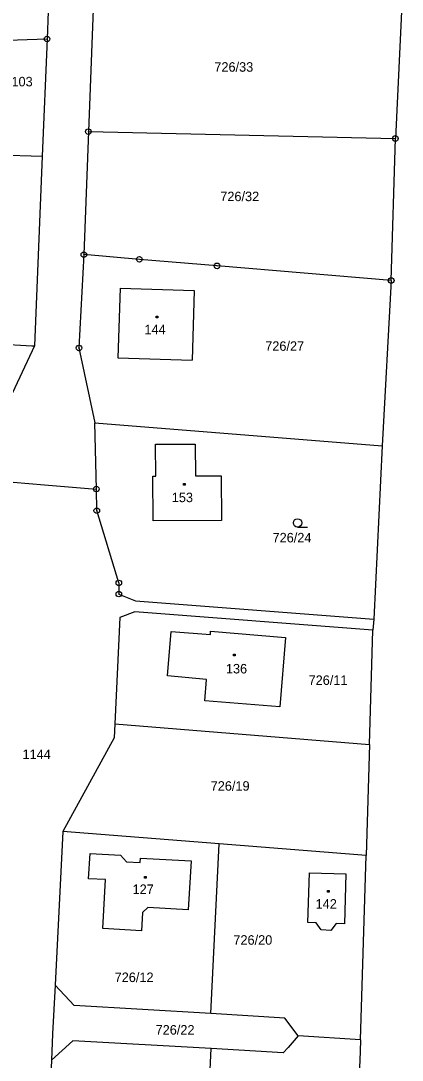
# Model space of a CAD drawing. Extents: x -794142 to -791199, y -1109267 to -1105626.
# Drawn here: x -793214.3 to -793146.2, y -1107931.8 to -1107745.8 of the extents above; entities that cross this region are included whole.
import ezdxf

# ---------------------------------------------------------------- set-up
doc = ezdxf.new("R2010")
doc.units = 0
for name, color, linetype in [('Vrstva 1', 7, 'Continuous'), ('Vrstva 14', 7, 'Continuous'), ('Vrstva 15', 7, 'Continuous'), ('Vrstva 23', 7, 'Continuous'), ('Vrstva 25', 7, 'Continuous'), ('Vrstva 28', 7, 'Continuous')]:
    doc.layers.add(name, color=color, linetype=linetype)

msp = doc.modelspace()

# ---------------------------------------------------------------- linework, layer by layer
at = {"layer": 'Vrstva 1'}
for p, q in [((-793146.16, -1107741.39), (-793147.38, -1107766.85)), ((-793209.44, -1107744.14), (-793209.64, -1107749.04)), ((-793201.42, -1107743.69), (-793202.25, -1107765.62)), ((-793221.25, -1107749.43), (-793209.64, -1107749.04)), ((-793209.64, -1107749.04), (-793210.51, -1107769.99)), ((-793202.25, -1107765.62), (-793203.07, -1107787.63)), ((-793202.25, -1107765.62), (-793147.38, -1107766.85)), ((-793148.12, -1107792.27), (-793147.38, -1107766.85)), ((-793220.37, -1107769.71), (-793210.51, -1107769.99)), ((-793210.51, -1107769.99), (-793211.88, -1107803.94)), ((-793203.07, -1107787.63), (-793203.93, -1107804.33)), ((-793193.13, -1107788.47), (-793203.07, -1107787.63)), ((-793179.26, -1107789.64), (-793193.13, -1107788.47)), ((-793148.12, -1107792.27), (-793179.26, -1107789.64)), ((-793148.12, -1107792.27), (-793149.73, -1107821.84)), ((-793196.55, -1107793.64), (-793196.97, -1107806.08)), ((-793196.55, -1107793.64), (-793183.32, -1107794.07)), ((-793183.32, -1107794.07), (-793183.72, -1107806.51)), ((-793211.88, -1107803.94), (-793223.04, -1107827.73)), ((-793222.21, -1107803.43), (-793212.38, -1107803.92)), ((-793212.38, -1107803.92), (-793211.88, -1107803.94)), ((-793203.93, -1107804.33), (-793201.08, -1107817.72)), ((-793196.97, -1107806.08), (-793183.72, -1107806.51)), ((-793201.08, -1107817.72), (-793149.73, -1107821.84)), ((-793200.83, -1107829.58), (-793201.08, -1107817.72)), ((-793190.24, -1107821.57), (-793183.16, -1107821.52)), ((-793183.16, -1107821.52), (-793183.11, -1107827.22)), ((-793190.2, -1107827.27), (-793190.24, -1107821.57)), ((-793149.73, -1107821.84), (-793151.23, -1107852.83)), ((-793223.04, -1107827.73), (-793210.07, -1107828.81)), ((-793210.07, -1107828.81), (-793200.83, -1107829.58)), ((-793190.67, -1107835.29), (-793190.73, -1107827.27)), ((-793190.73, -1107827.27), (-793190.2, -1107827.27)), ((-793183.11, -1107827.22), (-793178.5, -1107827.18)), ((-793178.5, -1107827.18), (-793178.43, -1107835.19)), ((-793200.75, -1107833.44), (-793200.83, -1107829.58)), ((-793196.81, -1107846.37), (-793200.75, -1107833.44)), ((-793178.43, -1107835.19), (-793190.67, -1107835.29)), ((-793196.81, -1107846.37), (-793196.81, -1107848.36)), ((-793196.81, -1107848.36), (-793193.82, -1107849.58)), ((-793193.82, -1107849.58), (-793151.23, -1107852.83)), ((-793196.63, -1107852.57), (-793197.54, -1107871.61)), ((-793193.97, -1107851.57), (-793196.63, -1107852.57)), ((-793151.38, -1107854.83), (-793193.97, -1107851.57)), ((-793151.23, -1107852.83), (-793151.38, -1107854.83)), ((-793152, -1107875.31), (-793151.38, -1107854.83)), ((-793188.09, -1107863.02), (-793187.43, -1107855.04)), ((-793187.43, -1107855.04), (-793180.45, -1107855.6)), ((-793180.45, -1107855.6), (-793180.4, -1107855.03)), ((-793180.4, -1107855.03), (-793166.99, -1107856.13)), ((-793166.99, -1107856.13), (-793168.04, -1107868.53)), ((-793181.12, -1107863.64), (-793188.09, -1107863.02)), ((-793181.44, -1107867.46), (-793181.12, -1107863.64)), ((-793168.04, -1107868.53), (-793181.44, -1107867.46)), ((-793197.54, -1107871.61), (-793197.66, -1107874.08)), ((-793197.54, -1107871.61), (-793152, -1107875.31)), ((-793197.66, -1107874.08), (-793206.8, -1107890.84)), ((-793152, -1107875.31), (-793152.61, -1107895.15)), ((-793206.8, -1107890.84), (-793208.2, -1107918.34)), ((-793178.86, -1107893.06), (-793206.8, -1107890.84)), ((-793180.34, -1107923.43), (-793178.86, -1107893.06)), ((-793152.61, -1107895.15), (-793178.86, -1107893.06)), ((-793202.21, -1107899.32), (-793201.93, -1107894.81)), ((-793201.93, -1107894.81), (-793196.51, -1107895.09)), ((-793196.51, -1107895.09), (-793195.46, -1107896.27)), ((-793192.97, -1107896.42), (-793192.92, -1107895.61)), ((-793192.92, -1107895.61), (-793183.9, -1107896.12)), ((-793153.61, -1107928.12), (-793152.61, -1107895.15)), ((-793195.46, -1107896.27), (-793192.97, -1107896.42)), ((-793183.9, -1107896.12), (-793184.4, -1107904.88)), ((-793199.18, -1107899.44), (-793202.21, -1107899.32)), ((-793199.66, -1107908.2), (-793199.18, -1107899.44)), ((-793163.04, -1107907.15), (-793162.75, -1107898.25)), ((-793162.75, -1107898.25), (-793156.24, -1107898.42)), ((-793156.24, -1107898.42), (-793156.48, -1107907.36)), ((-793191.63, -1107904.47), (-793192.59, -1107905.34)), ((-793184.4, -1107904.88), (-793191.63, -1107904.47)), ((-793192.59, -1107905.34), (-793192.77, -1107908.6)), ((-793192.77, -1107908.6), (-793199.66, -1107908.2)), ((-793161.55, -1107907.17), (-793163.04, -1107907.15)), ((-793160.65, -1107908.46), (-793161.55, -1107907.17)), ((-793158.92, -1107908.58), (-793160.65, -1107908.46)), ((-793157.99, -1107907.29), (-793158.92, -1107908.58)), ((-793156.48, -1107907.36), (-793157.99, -1107907.29)), ((-793208.2, -1107918.34), (-793208.64, -1107927.03)), ((-793208.2, -1107918.34), (-793204.81, -1107922.01)), ((-793180.34, -1107923.43), (-793204.81, -1107922.01)), ((-793167.12, -1107924.24), (-793180.34, -1107923.43)), ((-793164.73, -1107927.44), (-793167.12, -1107924.24)), ((-793208.64, -1107927.03), (-793208.85, -1107931.74)), ((-793164.73, -1107927.44), (-793166.57, -1107929.48)), ((-793153.61, -1107928.12), (-793164.73, -1107927.44)), ((-793208.85, -1107931.74), (-793205.04, -1107928.3)), ((-793180.28, -1107929.68), (-793205.04, -1107928.3)), ((-793153.61, -1107928.12), (-793153.68, -1107930.23)), ((-793181.98, -1107960.33), (-793180.28, -1107929.68)), ((-793167.46, -1107930.48), (-793180.28, -1107929.68)), ((-793166.57, -1107929.48), (-793167.46, -1107930.48)), ((-793153.68, -1107930.23), (-793155, -1107961.83)), ((-793208.85, -1107931.74), (-793210.02, -1107958.77))]:
    msp.add_line(p, q, dxfattribs=at)
at = {"layer": 'Vrstva 23'}
msp.add_line((-793164.85, -1107836.38), (-793163.1, -1107836.38), dxfattribs=at)
msp.add_circle((-793164.85, -1107835.63), 0.75, dxfattribs=at)
at = {"layer": 'Vrstva 25'}
for p, q in [((-793190.14, -1107798.66), (-793189.84, -1107798.66)), ((-793190.14, -1107798.96), (-793190.14, -1107798.66)), ((-793189.84, -1107798.96), (-793190.14, -1107798.96)), ((-793189.84, -1107798.66), (-793189.84, -1107798.96)), ((-793185.25, -1107828.57), (-793184.95, -1107828.57)), ((-793185.25, -1107828.87), (-793185.25, -1107828.57)), ((-793184.95, -1107828.87), (-793185.25, -1107828.87)), ((-793184.95, -1107828.57), (-793184.95, -1107828.87)), ((-793176.29, -1107859.14), (-793175.99, -1107859.14)), ((-793176.29, -1107859.44), (-793176.29, -1107859.14)), ((-793175.99, -1107859.44), (-793176.29, -1107859.44)), ((-793175.99, -1107859.14), (-793175.99, -1107859.44)), ((-793192.23, -1107898.89), (-793191.93, -1107898.89)), ((-793192.23, -1107899.19), (-793192.23, -1107898.89)), ((-793191.93, -1107899.19), (-793192.23, -1107899.19)), ((-793191.93, -1107898.89), (-793191.93, -1107899.19)), ((-793159.51, -1107901.38), (-793159.21, -1107901.38)), ((-793159.51, -1107901.68), (-793159.51, -1107901.38)), ((-793159.21, -1107901.38), (-793159.21, -1107901.68)), ((-793159.21, -1107901.68), (-793159.51, -1107901.68))]:
    msp.add_line(p, q, dxfattribs=at)
at = {"layer": 'Vrstva 28'}
for centre, radius in [((-793209.64, -1107749.04), 0.5), ((-793209.64, -1107749.04), 0.01), ((-793202.25, -1107765.62), 0.5), ((-793202.25, -1107765.62), 0.01), ((-793147.38, -1107766.85), 0.5), ((-793147.38, -1107766.85), 0.01), ((-793203.07, -1107787.63), 0.5), ((-793203.07, -1107787.63), 0.01), ((-793193.13, -1107788.47), 0.5), ((-793193.13, -1107788.47), 0.01), ((-793179.26, -1107789.64), 0.5), ((-793179.26, -1107789.64), 0.01), ((-793148.12, -1107792.27), 0.5), ((-793148.12, -1107792.27), 0.01), ((-793203.93, -1107804.33), 0.5), ((-793203.93, -1107804.33), 0.01), ((-793200.83, -1107829.58), 0.5), ((-793200.83, -1107829.58), 0.01), ((-793200.75, -1107833.44), 0.5), ((-793200.75, -1107833.44), 0.01), ((-793196.81, -1107846.37), 0.5), ((-793196.81, -1107846.37), 0.01), ((-793196.81, -1107848.36), 0.5), ((-793196.81, -1107848.36), 0.01)]:
    msp.add_circle(centre, radius, dxfattribs=at)

# ---------------------------------------------------------------- texts
at = {"layer": 'Vrstva 14'}
for s, p in [('726/33', (-793179.736, -1107754.9)), ('726/103', (-793220.429, -1107757.52)), ('726/32', (-793178.676, -1107778.06)), ('726/27', (-793170.643, -1107804.84)), ('726/24', (-793169.332, -1107839.12)), ('726/11', (-793162.893, -1107864.62)), ('1144', (-793214.025, -1107877.88)), ('726/19', (-793180.39, -1107883.55)), ('726/20', (-793176.335, -1107911.11)), ('726/12', (-793197.559, -1107917.79)), ('726/22', (-793190.236, -1107927.19))]:
    msp.add_text(s, height=1.7, dxfattribs=at).set_placement(p)
at = {"layer": 'Vrstva 15'}
for s, p in [('144', (-793192.232, -1107801.87)), ('153', (-793187.346, -1107831.92)), ('136', (-793177.67, -1107862.57)), ('127', (-793194.356, -1107902.03)), ('142', (-793161.636, -1107904.65))]:
    msp.add_text(s, height=1.7, dxfattribs=at).set_placement(p)

doc.saveas('drawing.dxf')
